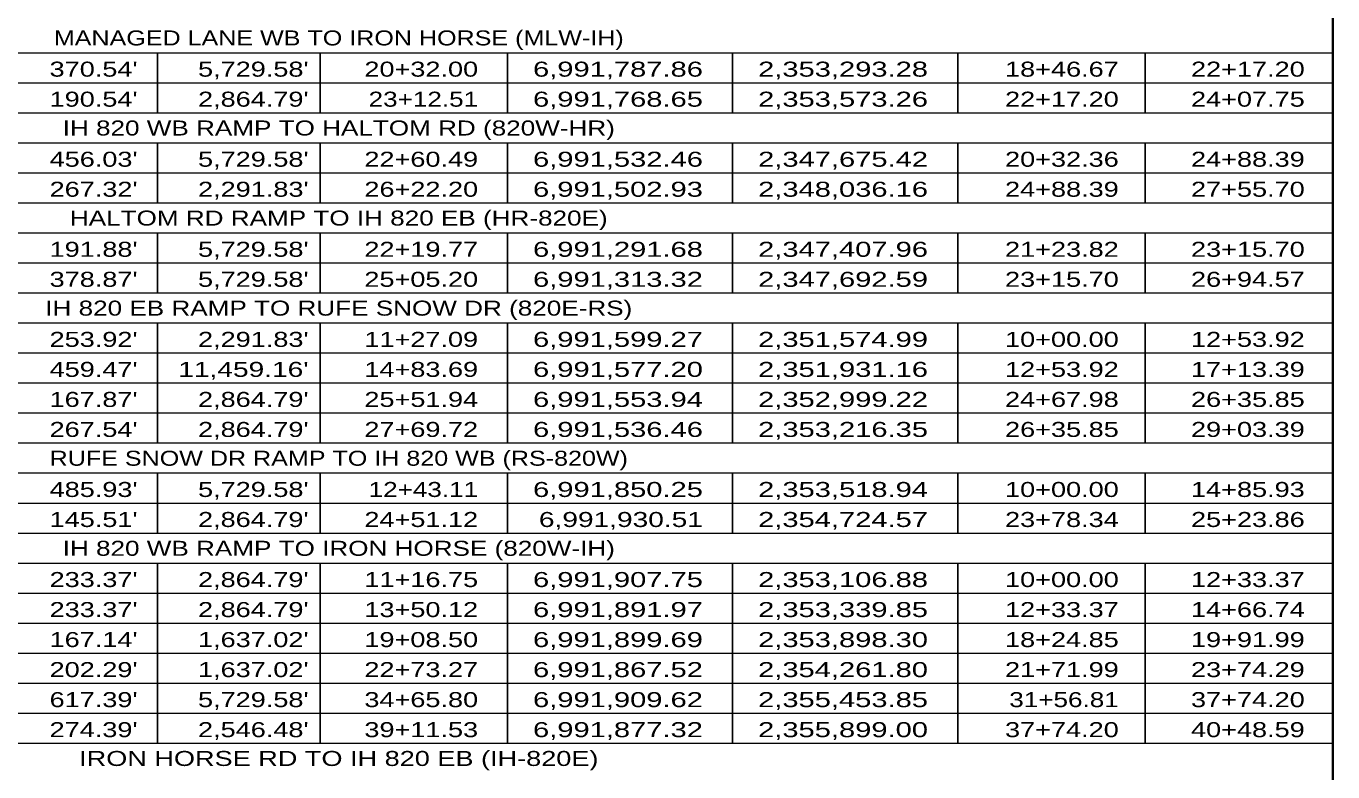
# Model space of a CAD drawing. Extents: x 1953053 to 1967065, y 7363860 to 7371201.
# Drawn here: x 1960635 to 1961680, y 7368761 to 7369357 of the extents above; entities that cross this region are included whole.
import ezdxf
from ezdxf.enums import TextEntityAlignment as Align

# ---------------------------------------------------------------- set-up
doc = ezdxf.new("R2010")
doc.units = 0
doc.header["$LTSCALE"] = 4.8
doc.layers.add('10', color=7, linetype='Continuous')
doc.layers.add('12', color=7, linetype='Continuous', lineweight=25)

msp = doc.modelspace()

# ---------------------------------------------------------------- linework, layer by layer
at = {"layer": '12', "lineweight": 35}
for p, q in [((1961680.213, 7368159.747), (1961680.213, 7370164.879)), ((1961680.213, 7368111.747), (1961680.213, 7370116.879))]:
    msp.add_line(p, q, dxfattribs=at)
at = {"layer": '12', "lineweight": 13}
for p, q in [((1959956.881, 7369335.746), (1961680.213, 7369335.746)), ((1959956.881, 7369311.746), (1961680.213, 7369311.746)), ((1959956.881, 7369287.746), (1961680.213, 7369287.746)), ((1959956.881, 7369263.746), (1961680.213, 7369263.746)), ((1959956.881, 7369239.746), (1961680.213, 7369239.746)), ((1959956.881, 7369215.746), (1961680.213, 7369215.746)), ((1959956.881, 7369191.746), (1961680.213, 7369191.746)), ((1959956.881, 7369167.746), (1961680.213, 7369167.746)), ((1959956.881, 7369143.746), (1961680.213, 7369143.746)), ((1959956.881, 7369119.746), (1961680.213, 7369119.746)), ((1959956.881, 7369095.746), (1961680.213, 7369095.746)), ((1959956.881, 7369071.746), (1961680.213, 7369071.746)), ((1959956.881, 7369047.746), (1961680.213, 7369047.746)), ((1959956.881, 7369023.746), (1961680.213, 7369023.746)), ((1959956.881, 7368999.746), (1961680.213, 7368999.746)), ((1959956.881, 7368975.746), (1961680.213, 7368975.746)), ((1959956.881, 7368951.746), (1961680.213, 7368951.746)), ((1959956.881, 7368927.746), (1961680.213, 7368927.746)), ((1959956.881, 7368903.746), (1961680.213, 7368903.746)), ((1959956.881, 7368879.746), (1961680.213, 7368879.746)), ((1959956.881, 7368855.746), (1961680.213, 7368855.746)), ((1959956.881, 7368831.747), (1961680.213, 7368831.747)), ((1959956.881, 7368807.747), (1961680.213, 7368807.747)), ((1959956.881, 7368783.747), (1961680.213, 7368783.747))]:
    msp.add_line(p, q, dxfattribs=at)
at = {"layer": '12'}
for p, q in [((1960740.213, 7369335.746), (1960740.213, 7369287.746)), ((1960870.213, 7369335.746), (1960870.213, 7369287.746)), ((1961020.213, 7369335.746), (1961020.213, 7369287.746)), ((1961200.213, 7369335.746), (1961200.213, 7369287.746)), ((1961380.213, 7369335.746), (1961380.213, 7369287.746)), ((1961530.213, 7369335.746), (1961530.213, 7369287.746)), ((1960740.213, 7369263.746), (1960740.213, 7369215.746)), ((1960870.213, 7369263.746), (1960870.213, 7369215.746)), ((1961020.213, 7369263.746), (1961020.213, 7369215.746)), ((1961200.213, 7369263.746), (1961200.213, 7369215.746)), ((1961380.213, 7369263.746), (1961380.213, 7369215.746)), ((1961530.213, 7369263.746), (1961530.213, 7369215.746)), ((1960740.213, 7369191.746), (1960740.213, 7369143.746)), ((1960870.213, 7369191.746), (1960870.213, 7369143.746)), ((1961020.213, 7369191.746), (1961020.213, 7369143.746)), ((1961200.213, 7369191.746), (1961200.213, 7369143.746)), ((1961380.213, 7369191.746), (1961380.213, 7369143.746)), ((1961530.213, 7369191.746), (1961530.213, 7369143.746)), ((1960740.213, 7369119.746), (1960740.213, 7369023.746)), ((1960870.213, 7369119.746), (1960870.213, 7369023.746)), ((1961020.213, 7369119.746), (1961020.213, 7369023.746)), ((1961200.213, 7369119.746), (1961200.213, 7369023.746)), ((1961380.213, 7369119.746), (1961380.213, 7369023.746)), ((1961530.213, 7369119.746), (1961530.213, 7369023.746)), ((1960740.213, 7368999.746), (1960740.213, 7368951.746)), ((1960870.213, 7368999.746), (1960870.213, 7368951.746)), ((1961020.213, 7368999.746), (1961020.213, 7368951.746)), ((1961200.213, 7368999.746), (1961200.213, 7368951.746)), ((1961380.213, 7368999.746), (1961380.213, 7368951.746)), ((1961530.213, 7368999.746), (1961530.213, 7368951.746)), ((1960740.213, 7368927.746), (1960740.213, 7368783.747)), ((1960870.213, 7368927.746), (1960870.213, 7368783.747)), ((1961020.213, 7368927.746), (1961020.213, 7368783.747)), ((1961200.213, 7368927.746), (1961200.213, 7368783.747)), ((1961380.213, 7368927.746), (1961380.213, 7368783.747)), ((1961530.213, 7368927.746), (1961530.213, 7368783.747))]:
    msp.add_line(p, q, dxfattribs=at)

# ---------------------------------------------------------------- texts
at = {"layer": '10'}
for s, width, p in [('MANAGED LANE WB TO IRON HORSE (MLW-IH)', 1.25, (1960885.213, 7369341.54)), ('IH 820 WB RAMP TO HALTOM RD (820W-HR)', 1.3, (1960885.213, 7369269.54)), ('HALTOM RD RAMP TO IH 820 EB (HR-820E)', 1.3, (1960885.213, 7369197.54)), ('IH 820 EB RAMP TO RUFE SNOW DR (820E-RS)', 1.3, (1960885.213, 7369125.54)), ('RUFE SNOW DR RAMP TO IH 820 WB (RS-820W)', 1.25, (1960885.213, 7369005.54)), ('IH 820 WB RAMP TO IRON HORSE (820W-IH)', 1.3, (1960885.214, 7368933.54)), ('IRON HORSE RD TO IH 820 EB (IH-820E)', 1.35, (1960885.213, 7368765.541))]:
    msp.add_text(s, height=12, dxfattribs=dict(at, width=width)).set_placement(p, align=Align.CENTER)
for s, width, p in [("370.54'", 1.35, (1960724.337, 7369316.573)), ("5,729.58'", 1.35, (1960861.106, 7369316.573)), ('20+32.00', 1.35, (1960996.65, 7369316.573)), ('6,991,787.86', 1.45, (1961176.415, 7369316.573)), ('2,353,293.28', 1.45, (1961356.415, 7369316.573)), ('18+46.67', 1.35, (1961508.993, 7369316.573)), ('22+17.20', 1.35, (1961657.725, 7369316.573)), ("190.54'", 1.35, (1960724.337, 7369292.573)), ("2,864.79'", 1.35, (1960861.106, 7369292.573)), ('23+12.51', 1.3, (1960996.65, 7369292.573)), ('6,991,768.65', 1.45, (1961176.415, 7369292.573)), ('2,353,573.26', 1.45, (1961356.415, 7369292.573)), ('22+17.20', 1.35, (1961508.993, 7369292.573)), ('24+07.75', 1.35, (1961657.725, 7369292.573)), ("456.03'", 1.35, (1960724.339, 7369244.572)), ("5,729.58'", 1.35, (1960861.108, 7369244.572)), ('22+60.49', 1.35, (1960996.652, 7369244.572)), ('6,991,532.46', 1.45, (1961176.417, 7369244.572)), ('2,347,675.42', 1.45, (1961356.417, 7369244.572)), ('20+32.36', 1.35, (1961508.995, 7369244.572)), ('24+88.39', 1.35, (1961657.727, 7369244.572)), ("267.32'", 1.35, (1960724.339, 7369220.572)), ("2,291.83'", 1.35, (1960861.108, 7369220.572)), ('26+22.20', 1.35, (1960996.652, 7369220.572)), ('6,991,502.93', 1.45, (1961176.417, 7369220.572)), ('2,348,036.16', 1.45, (1961356.417, 7369220.572)), ('24+88.39', 1.35, (1961508.995, 7369220.572)), ('27+55.70', 1.35, (1961657.727, 7369220.572)), ("191.88'", 1.35, (1960724.339, 7369172.572)), ("5,729.58'", 1.35, (1960861.108, 7369172.572)), ('22+19.77', 1.35, (1960996.652, 7369172.572)), ('6,991,291.68', 1.45, (1961176.417, 7369172.572)), ('2,347,407.96', 1.45, (1961356.417, 7369172.572)), ('21+23.82', 1.35, (1961508.995, 7369172.572)), ('23+15.70', 1.35, (1961657.727, 7369172.572)), ("378.87'", 1.35, (1960724.339, 7369148.572)), ("5,729.58'", 1.35, (1960861.108, 7369148.572)), ('25+05.20', 1.35, (1960996.652, 7369148.572)), ('6,991,313.32', 1.45, (1961176.417, 7369148.572)), ('2,347,692.59', 1.45, (1961356.417, 7369148.572)), ('23+15.70', 1.35, (1961508.995, 7369148.572)), ('26+94.57', 1.35, (1961657.727, 7369148.572)), ("253.92'", 1.35, (1960724.337, 7369100.573)), ("2,291.83'", 1.35, (1960861.106, 7369100.573)), ('11+27.09', 1.35, (1960996.65, 7369100.573)), ('6,991,599.27', 1.45, (1961176.415, 7369100.573)), ('2,351,574.99', 1.45, (1961356.415, 7369100.573)), ('10+00.00', 1.35, (1961508.993, 7369100.573)), ('12+53.92', 1.35, (1961657.725, 7369100.573)), ("459.47'", 1.35, (1960724.337, 7369076.573)), ("11,459.16'", 1.4, (1960861.106, 7369076.573)), ('14+83.69', 1.35, (1960996.65, 7369076.573)), ('6,991,577.20', 1.45, (1961176.415, 7369076.573)), ('2,351,931.16', 1.45, (1961356.415, 7369076.573)), ('12+53.92', 1.35, (1961508.993, 7369076.573)), ('17+13.39', 1.35, (1961657.725, 7369076.573)), ("167.87'", 1.35, (1960724.337, 7369052.573)), ("2,864.79'", 1.35, (1960861.106, 7369052.573)), ('25+51.94', 1.35, (1960996.65, 7369052.573)), ('6,991,553.94', 1.45, (1961176.415, 7369052.573)), ('2,352,999.22', 1.45, (1961356.415, 7369052.573)), ('24+67.98', 1.35, (1961508.993, 7369052.573)), ('26+35.85', 1.35, (1961657.725, 7369052.573)), ("267.54'", 1.35, (1960724.337, 7369028.573)), ("2,864.79'", 1.35, (1960861.106, 7369028.573)), ('27+69.72', 1.35, (1960996.65, 7369028.573)), ('6,991,536.46', 1.45, (1961176.415, 7369028.573)), ('2,353,216.35', 1.45, (1961356.415, 7369028.573)), ('26+35.85', 1.35, (1961508.993, 7369028.573)), ('29+03.39', 1.35, (1961657.725, 7369028.573)), ("485.93'", 1.35, (1960724.337, 7368980.573)), ("5,729.58'", 1.35, (1960861.106, 7368980.573)), ('12+43.11', 1.3, (1960996.65, 7368980.573)), ('6,991,850.25', 1.45, (1961176.415, 7368980.573)), ('2,353,518.94', 1.45, (1961356.415, 7368980.573)), ('10+00.00', 1.35, (1961508.993, 7368980.573)), ('14+85.93', 1.35, (1961657.725, 7368980.573)), ("145.51'", 1.35, (1960724.337, 7368956.573)), ("2,864.79'", 1.35, (1960861.106, 7368956.573)), ('24+51.12', 1.35, (1960996.65, 7368956.573)), ('6,991,930.51', 1.4, (1961176.415, 7368956.573)), ('2,354,724.57', 1.45, (1961356.415, 7368956.573)), ('23+78.34', 1.35, (1961508.993, 7368956.573)), ('25+23.86', 1.35, (1961657.725, 7368956.573)), ("233.37'", 1.35, (1960724.337, 7368908.573)), ("2,864.79'", 1.35, (1960861.106, 7368908.573)), ('11+16.75', 1.35, (1960996.65, 7368908.573)), ('6,991,907.75', 1.45, (1961176.415, 7368908.573)), ('2,353,106.88', 1.45, (1961356.415, 7368908.573)), ('10+00.00', 1.35, (1961508.993, 7368908.573)), ('12+33.37', 1.35, (1961657.725, 7368908.573)), ("233.37'", 1.35, (1960724.337, 7368884.573)), ("2,864.79'", 1.35, (1960861.106, 7368884.573)), ('13+50.12', 1.35, (1960996.65, 7368884.573)), ('6,991,891.97', 1.45, (1961176.415, 7368884.573)), ('2,353,339.85', 1.45, (1961356.415, 7368884.573)), ('12+33.37', 1.35, (1961508.993, 7368884.573)), ('14+66.74', 1.35, (1961657.725, 7368884.573)), ("167.14'", 1.35, (1960724.337, 7368860.573)), ("1,637.02'", 1.35, (1960861.106, 7368860.573)), ('19+08.50', 1.35, (1960996.65, 7368860.573)), ('6,991,899.69', 1.45, (1961176.415, 7368860.573)), ('2,353,898.30', 1.45, (1961356.415, 7368860.573)), ('18+24.85', 1.35, (1961508.993, 7368860.573)), ('19+91.99', 1.35, (1961657.725, 7368860.573)), ("202.29'", 1.35, (1960724.337, 7368836.573)), ("1,637.02'", 1.35, (1960861.106, 7368836.573)), ('22+73.27', 1.35, (1960996.65, 7368836.573)), ('6,991,867.52', 1.45, (1961176.415, 7368836.573)), ('2,354,261.80', 1.45, (1961356.415, 7368836.573)), ('21+71.99', 1.35, (1961508.993, 7368836.573)), ('23+74.29', 1.35, (1961657.725, 7368836.573)), ("617.39'", 1.35, (1960724.337, 7368812.573)), ("5,729.58'", 1.35, (1960861.106, 7368812.573)), ('34+65.80', 1.35, (1960996.65, 7368812.573)), ('6,991,909.62', 1.45, (1961176.415, 7368812.573)), ('2,355,453.85', 1.45, (1961356.415, 7368812.573)), ('31+56.81', 1.3, (1961508.993, 7368812.573)), ('37+74.20', 1.35, (1961657.725, 7368812.573)), ("274.39'", 1.35, (1960724.337, 7368788.573)), ("2,546.48'", 1.35, (1960861.106, 7368788.573)), ('39+11.53', 1.35, (1960996.65, 7368788.573)), ('6,991,877.32', 1.45, (1961176.415, 7368788.573)), ('2,355,899.00', 1.45, (1961356.415, 7368788.573)), ('37+74.20', 1.35, (1961508.993, 7368788.573)), ('40+48.59', 1.35, (1961657.725, 7368788.573))]:
    msp.add_text(s, height=12, dxfattribs=dict(at, width=width)).set_placement(p, align=Align.RIGHT)

doc.saveas('drawing.dxf')
